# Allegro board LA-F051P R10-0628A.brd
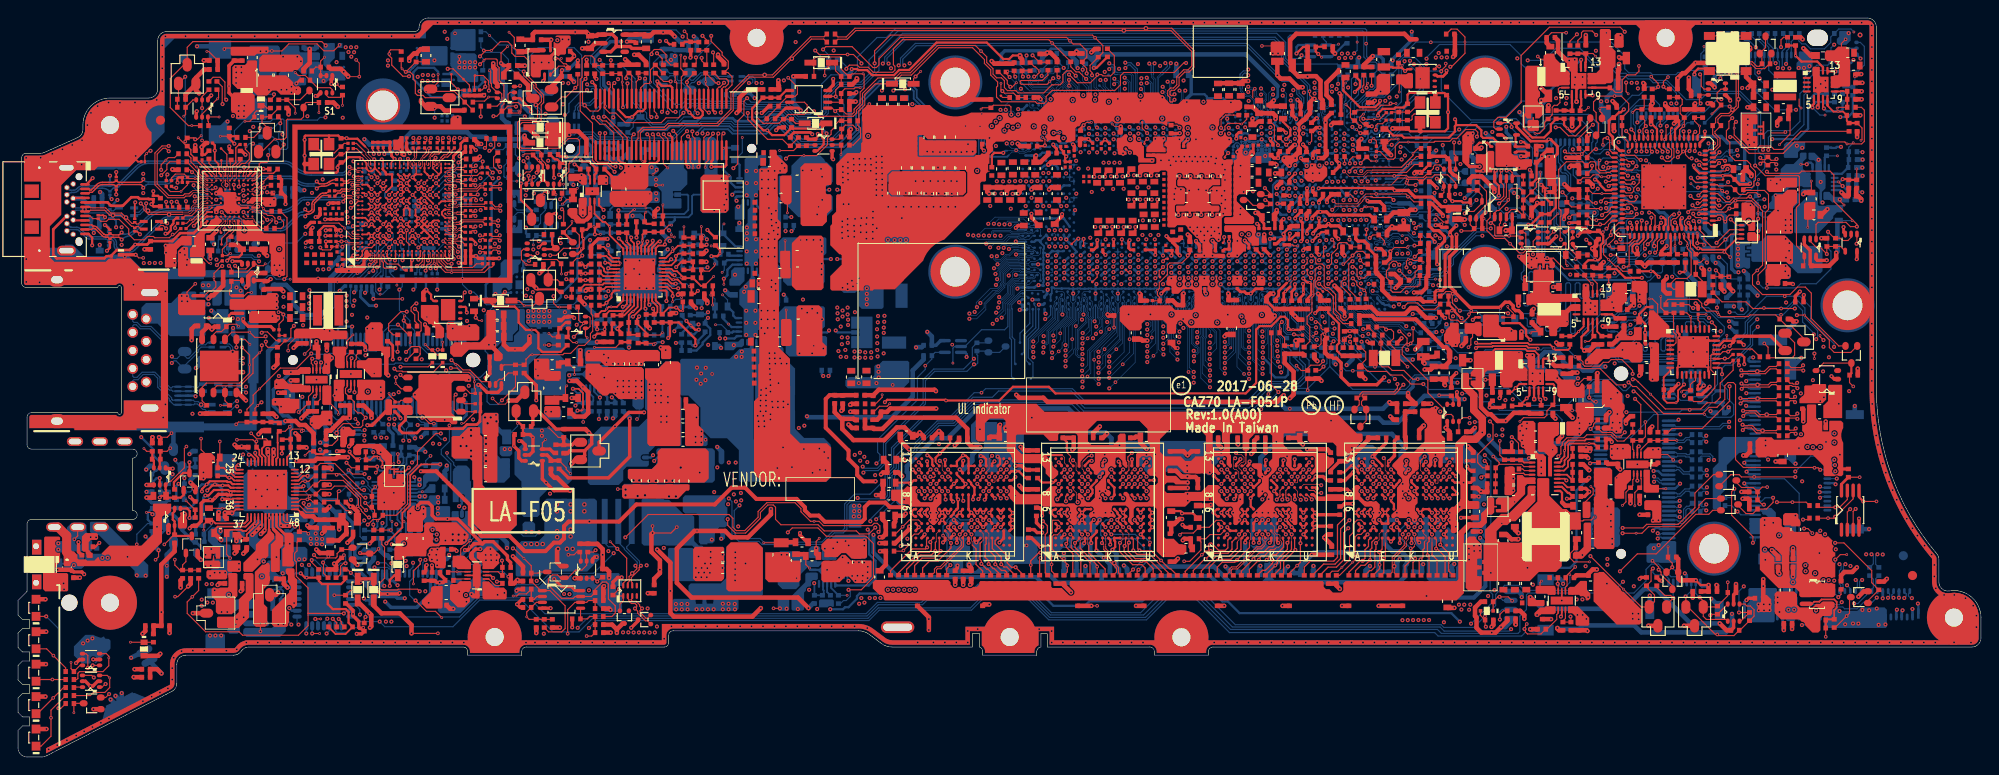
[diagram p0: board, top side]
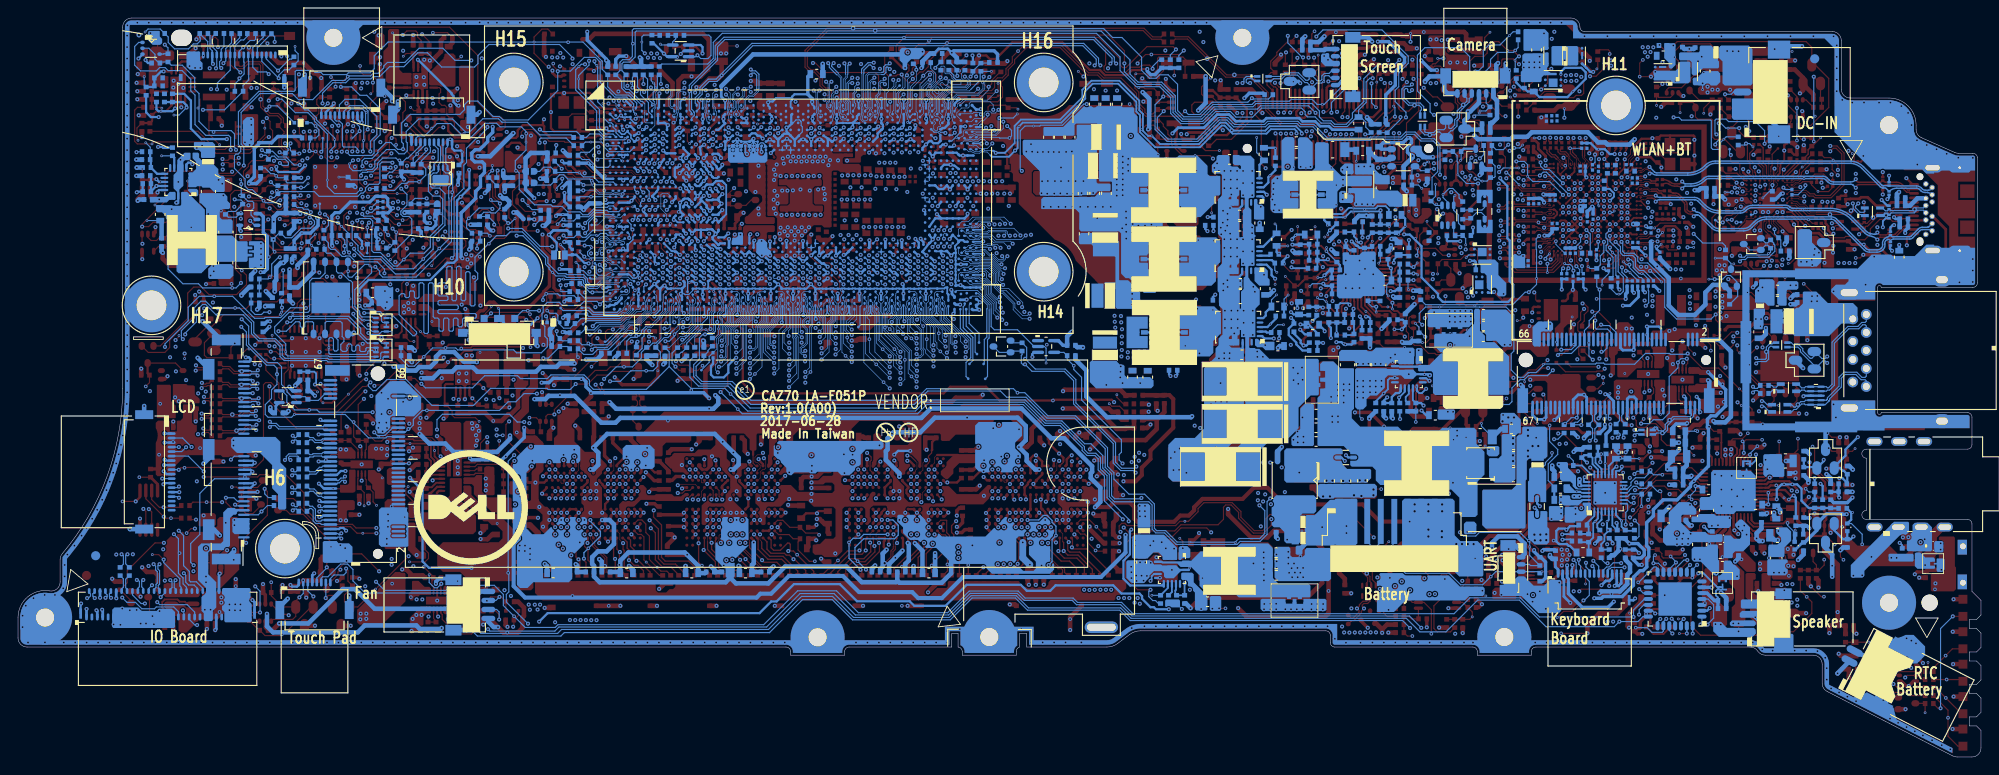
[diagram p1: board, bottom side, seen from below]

Outline 217.81 x 82 mm; copper layers: TOP, GND1, IN1, GND2, IN2, IN3, VCC, IN4, GND3, BOTTOM. Coordinates in mm from the lower left corner of the outline.
Outline path: 0,17.38 1,18.38 1,25.86 arc(1.15,26.21) 1.5,26.36 12.72,26.36 arc(13.22,26.86) 12.72,27.36 12.72,33.16 arc(13.22,33.66) 12.72,34.16 1.5,34.16 arc(1.15,34.31) 1,34.66 1,37.71 arc(1.15,38.06) 1.5,38.21 11.07,38.21 arc(11.27,38.01) 11.47,38.21 11.47,52.11 arc(11.27,52.31) 11.07,52.11 0.9,52.11 arc(0.55,52.26) 0.4,52.61 0.4,66.49 arc(0.55,66.84) 0.9,66.99 2.49,66.99 arc(2.7,67.01) 2.9,67.08 6.61,68.73 arc(7.04,69.09) 7.2,69.64 7.2,70.12 arc(8.08,72.24) 10.2,73.12 14.5,73.12 arc(15.21,73.41) 15.5,74.12 15.5,79.5 arc(15.79,80.21) 16.5,80.5 44,80.5 arc(44.35,80.65) 44.5,81 arc(44.79,81.71) 45.5,82 205.2,82 arc(205.91,81.71) 206.2,81 206.2,40.92 arc(207.93,31.15) 212.9,22.56 arc(213.08,22.26) 213.14,21.91 213.14,19.41 arc(213.49,18.65) 214.31,18.43 arc(216.75,17.76) 217.81,15.47 217.81,13.2 arc(217.52,12.49) 216.81,12.2 132.59,12.2 arc(132.24,12.05) 132.09,11.7 132.09,11.3 126.09,11.3 126.09,11.7 arc(125.94,12.05) 125.59,12.2 114.2,12.2 114.2,13.7 113.5,13.7 113.5,12.2 arc(113.17,12.04) 113.04,11.7 113.04,11.3 107.04,11.3 107.04,11.72 arc(106.94,12.02) 106.68,12.2 106.68,13.7 105.88,13.7 105.88,12.2 96.99,12.2 arc(96.36,12.3) 95.79,12.6 94.46,13.6 arc(93.89,13.9) 93.26,14 72.7,14 arc(72.35,13.85) 72.2,13.5 72.2,12.7 arc(72.05,12.35) 71.7,12.2 56.39,12.2 arc(56.04,12.05) 55.89,11.7 55.89,11.3 49.89,11.3 49.89,11.7 arc(49.74,12.05) 49.39,12.2 25.61,12.2 arc(25.14,12.08) 24.78,11.75 arc(24.41,11.42) 23.94,11.3 18.62,11.3 arc(17.91,11.01) 17.62,10.3 17.62,8.17 arc(17.47,7.65) 17.08,7.28 3.12,0.11 arc(2.89,0.03) 2.66,0 1,0 arc(0.29,0.29) 0,1 0,2.95 0.5,3.45 1.3,3.45 1.3,4.45 0.5,4.45 0,4.95 0,6.55 0.5,7.05 1.3,7.05 1.3,8.05 0.5,8.05 0,8.55 0,10.15 0.5,10.65 1.3,10.65 1.3,11.65 0.5,11.65 0,12.15 0,13.75 0.5,14.25 1.3,14.25 1.3,15.25 0.5,15.25 0,15.75 0,17.38

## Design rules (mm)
constraint set DEFAULT: min track width 0.127
net group 12C: nets I2C1_SDA I2C1_SDA_TP
net group CLK1_PCIE_WLAN: nets CLK1_PCIE_WLAN CLK1_PCIE_WLAN#
net group CLK_ITPXDP: nets CLK_ITPXDP_N CLK_ITPXDP_P
net group CLK_PCIE_MMI: nets CLK_PCIE_MMI CLK_PCIE_MMI#
net group CLK_PCIE_SSD: nets CLK_PCIE_SSD CLK_PCIE_SSD#
net group CLKO_PCIE_TBT: nets CLK0_PCIE_TBT CLK0_PCIE_TBT#
net group CPU_DDI1_AUX: nets CPU_DDI1_AUXN CPU_DDI1_AUXP
net group CPU_DDI2_AUX: nets CPU_DDI2_AUXN CPU_DDI2_AUXP
net group DDI1_PTX_TBRX_P0: nets DDI1_PTX_TBRX_N0 DDI1_PTX_TBRX_P0
net group DDI1_PTX_TBRX_P1: nets DDI1_PTX_TBRX_N1 DDI1_PTX_TBRX_P1
net group DDI1_PTX_TBRX_P2: nets DDI1_PTX_TBRX_N2 DDI1_PTX_TBRX_P2
net group DDI1_PTX_TBRX_P3: nets DDI1_PTX_TBRX_N3 DDI1_PTX_TBRX_P3
net group DDI2_PTX_TBRX_P0: nets DDI2_PTX_TBRX_N0 DDI2_PTX_TBRX_P0
net group DDI2_PTX_TBRX_P1: nets DDI2_PTX_TBRX_N1 DDI2_PTX_TBRX_P1
net group DDI2_PTX_TBRX_P2: nets DDI2_PTX_TBRX_N2 DDI2_PTX_TBRX_P2
net group DDI2_PTX_TBRX_P3: nets DDI2_PTX_TBRX_N3 DDI2_PTX_TBRX_P3
net group DIFFPAIR0: nets EDP_AUXN EDP_AUXP
net group DIFFPAIR2: nets EDP_AUXN_CONN EDP_AUXP_CONN
net group DIFFPAIR6: nets CPU_DDI1_AUXN_C CPU_DDI1_AUXP_C
net group DIFFPAIR7: nets CLK_ITPXDP_N_R CLK_ITPXDP_P_R
net group DIFFPAIR8: nets PCIE_PRX_TBTX_N1_C PCIE_PRX_TBTX_P1_C
net group DIFFPAIR9: nets PCIE_PRX_TBTX_N2_C PCIE_PRX_TBTX_P2_C
net group DIFFPAIR10: nets PCIE_PTX_CARDRX_N6_C PCIE_PTX_CARDRX_P6_C
net group DIFFPAIR11: nets PCIE_PTX_SSDRX_N11_C PCIE_PTX_SSDRX_P11_C
net group DIFFPAIR12: nets PCIE_PTX_SSDRX_N10_C PCIE_PTX_SSDRX_P10_C
net group DIFFPAIR13: nets PCIE_PTX_WLANRX_N5_C PCIE_PTX_WLANRX_P5_C
net group DIFFPAIR14: nets PCIE_PTX_SSDRX_N9_C PCIE_PTX_SSDRX_P9_C
net group DIFFPAIR15: nets PCIE_PTX_TBRX_N1_C PCIE_PTX_TBRX_P1_C
net group DIFFPAIR16: nets PCIE_PTX_TBRX_N2_C PCIE_PTX_TBRX_P2_C
net group DIFFPAIR17: nets USB20_N2_CONN USB20_P2_CONN
net group DIFFPAIR18: nets USB20_N3_R USB20_P3_R
net group DIFFPAIR19: nets USB20_N4_CONN USB20_P4_CONN
net group DIFFPAIR20: nets USB20_N5_CONN USB20_P5_CONN
net group DIFFPAIR21: nets USB3RN2_RC_CON USB3RP2_RC_CON
net group DIFFPAIR22: nets USB3TN2_C USB3TP2_C
net group DIFFPAIR23: nets USB3TN2_RC_CON USB3TP2_RC_CON
net group DP_CPU_DDI2_AUXN_C: nets CPU_DDI2_AUXN_C CPU_DDI2_AUXP_C
net group DP_EDP_TXN_P0_CONN: nets EDP_TXN_P0_CONN EDP_TXP_P0_CONN
net group DP_EDP_TXN_P1_CONN: nets EDP_TXN_P1_CONN EDP_TXP_P1_CONN
net group DP_EDP_TXN_P2_CONN: nets EDP_TXN_P2_CONN EDP_TXP_P2_CONN
net group DP_EDP_TXN_P3_CONN: nets EDP_TXN_P3_CONN EDP_TXP_P3_CONN
net group DP_TBT_I2C_B_N_R: nets TBT_I2C_B_N_R TBT_I2C_B_P_R
net group DP_TBT_USB2_T_N_R: nets TBT_USB2_T_N_R TBT_USB2_T_P_R
net group EDP_TX_P1: nets EDP_TXN_P1 EDP_TXP_P1
net group EDP_TX_P2: nets EDP_TXN_P2 EDP_TXP_P2
net group EDP_TX_P3: nets EDP_TXN_P3 EDP_TXP_P3
net group EPD_TX_P0: nets EDP_TXN_P0 EDP_TXP_P0
net group MEM_SMBCLKDATA: nets MEM_SMBCLK MEM_SMBDATA
net group PBAT_SMBCLKDAT: nets PBAT_SMBCLK PBAT_SMBDAT
net group PCIE_PRX_CARDTX_P6: nets PCIE_PRX_CARDTX_N6 PCIE_PRX_CARDTX_P6
net group PCIE_PRX_SSDTX_11: nets PCIE_PRX_SSDTX_N11 PCIE_PRX_SSDTX_P11
net group PCIE_PRX_SSDTX_P9: nets PCIE_PRX_SSDTX_N9 PCIE_PRX_SSDTX_P9
net group PCIE_PRX_SSDTX_P10: nets PCIE_PRX_SSDTX_N10 PCIE_PRX_SSDTX_P10
net group PCIE_PRX_TBTX_P1: nets PCIE_PRX_TBTX_N1 PCIE_PRX_TBTX_P1
net group PCIE_PRX_TBTX_P2: nets PCIE_PRX_TBTX_N2 PCIE_PRX_TBTX_P2
net group PCIE_PRX_WLANTX_P5: nets PCIE_PRX_WLANTX_N5 PCIE_PRX_WLANTX_P5
net group PCIE_PTX_CARDRX_P6: nets PCIE_PTX_CARDRX_N6 PCIE_PTX_CARDRX_P6
net group PCIE_PTX_SSDRX_11: nets PCIE_PTX_SSDRX_N11 PCIE_PTX_SSDRX_P11
net group PCIE_PTX_SSDRX_P9: nets PCIE_PTX_SSDRX_N9 PCIE_PTX_SSDRX_P9
net group PCIE_PTX_SSDRX_P10: nets PCIE_PTX_SSDRX_N10 PCIE_PTX_SSDRX_P10
net group PCIE_PTX_TBRX_P1: nets PCIE_PTX_TBRX_N1 PCIE_PTX_TBRX_P1
net group PCIE_PTX_TBRX_P2: nets PCIE_PTX_TBRX_N2 PCIE_PTX_TBRX_P2
net group PCIE_PTX_WLANRX_P5: nets PCIE_PTX_WLANRX_N5 PCIE_PTX_WLANRX_P5
net group REM_DIODE1: nets REM_DIODE1_N REM_DIODE1_P
net group REM_DIODE2: nets REM_DIODE2_N REM_DIODE2_P
net group REM_DIODE3: nets REM_DIODE3_N REM_DIODE3_P
net group REM_DIODE4: nets REM_DIODE4_N REM_DIODE4_P
net group SATA_PRX_SSDTX_2: nets SATA_PRX_SSDTX_N2 SATA_PRX_SSDTX_P2
net group SATA_PTX_SSDRX_2: nets SATA_PTX_SSDRX_N2 SATA_PTX_SSDRX_P2
net group SMB_CLKDAT: nets CLK_SMB DAT_SMB
net group SML1_SMBCLKDAT: nets SML1_SMBCLK SML1_SMBDAT
net group SPACING-18: nets PECI_EC PECI_EC_R
net group TBT_12C_CLKDATA: nets TBT_I2C_CLK TBT_I2C_DATA
net group TBT_I2C_B: nets TBT_I2C_B_N TBT_I2C_B_P
net group TBT_USB2_T: nets TBT_USB2_T_N TBT_USB2_T_P
net group TBT_USB3_RX1: nets TBT_USB3_RX1_N TBT_USB3_RX1_P
net group TBT_USB3_RXO_NP_R: nets TBT_USB3_RX0_N TBT_USB3_RX0_P
net group TBT_USB3_TX0_P_C: nets TBT_USB3_TX0_N_C TBT_USB3_TX0_P_C
net group TBT_USB3_TX1: nets TBT_USB3_TX1_N TBT_USB3_TX1_P
net group TBT_USB3_TX1_N_C: nets TBT_USB3_TX1_N_C TBT_USB3_TX1_P_C
net group TBT_USB3_TXO_P: nets TBT_USB3_TX0_N TBT_USB3_TX0_P
net group USB2.0_P1: nets USB20_N1 USB20_P1
net group USB2.0_P2: nets USB20_N2 USB20_P2
net group USB2.0_P3: nets USB20_N3 USB20_P3
net group USB2.0_P4: nets USB20_N4 USB20_P4
net group USB2.0_P5: nets USB20_N5 USB20_P5
net group USB3.0_R1: nets USB3RN1 USB3RP1
net group USB3.0_R2: nets USB3RN2 USB3RP2
net group USB3.0_T1: nets USB3TN1 USB3TP1
net group USB3.0_T2: nets USB3TN2 USB3TP2
net group USB_2.0: nets TBT_USB2_D_N TBT_USB2_D_P
net group 12C_15: nets HDA_BIT_CLK HDA_BIT_CLK_R I2C1_SCK I2C1_SCK_TP PCH_SPI_CLK PCH_SPI_CLK_TPM SPI_CLK_VROM
net group 24MHZ: nets CLK_LPC_DEBUG CLK_PCI_MEC PCI_CLK_LPC0 PCI_CLK_LPC1 XTAL24_IN XTAL24_OUT
net group COMP-20-25: nets SM_RCOMP0 SM_RCOMP1 SM_RCOMP2
net group DDRA_CKE: nets DDR_A_CKE0 DDR_A_CKE1 DDR_A_CKE2 DDR_A_CKE3
net group DDRB-D6: nets DDR_B_D48 DDR_B_D49 DDR_B_D50 DDR_B_D51 DDR_B_D52 DDR_B_D53 DDR_B_D54 DDR_B_D55
net group DDRB-D7: nets DDR_B_D56 DDR_B_D57 DDR_B_D58 DDR_B_D59 DDR_B_D60 DDR_B_D61 DDR_B_D62 DDR_B_D63
net group DDRB_CKE: nets DDR_B_CKE0 DDR_B_CKE1 DDR_B_CKE2 DDR_B_CKE3
net group DP1_AR_TBT: nets DDI1_PTX_TBRX_N0_C DDI1_PTX_TBRX_N1_C DDI1_PTX_TBRX_N2_C DDI1_PTX_TBRX_N3_C DDI1_PTX_TBRX_P0_C DDI1_PTX_TBRX_P1_C DDI1_PTX_TBRX_P2_C DDI1_PTX_TBRX_P3_C
net group DP2_AR_TBT: nets DDI2_PTX_TBRX_N0_C DDI2_PTX_TBRX_N1_C DDI2_PTX_TBRX_N2_C DDI2_PTX_TBRX_N3_C DDI2_PTX_TBRX_P0_C DDI2_PTX_TBRX_P1_C DDI2_PTX_TBRX_P2_C DDI2_PTX_TBRX_P3_C
net group HDA: nets HDA_SDIN0 HDA_SDOUT HDA_SDOUT_R HDA_SYNC HDA_SYNC_R
net group R_DDRA-CLK-UD19: nets DDR_A_DQS0 DDR_A_DQS1 DDR_A_DQS2 DDR_A_DQS3
net group R_DDRA-CLK-UD20: nets DDR_A_DQS4 DDR_A_DQS5 DDR_A_DQS6 DDR_A_DQS7
net group R_DDRA-D0: nets DDR_A_D0 DDR_A_D1 DDR_A_D2 DDR_A_D3 DDR_A_D4 DDR_A_D5 DDR_A_D6 DDR_A_D7
net group R_DDRA-D1: nets DDR_A_D8 DDR_A_D9 DDR_A_D10 DDR_A_D11 DDR_A_D12 DDR_A_D13 DDR_A_D14 DDR_A_D15
net group R_DDRA-D2: nets DDR_A_D16 DDR_A_D17 DDR_A_D18 DDR_A_D19 DDR_A_D20 DDR_A_D21 DDR_A_D22 DDR_A_D23
net group R_DDRA-D3: nets DDR_A_D24 DDR_A_D25 DDR_A_D26 DDR_A_D27 DDR_A_D28 DDR_A_D29 DDR_A_D30 DDR_A_D31
net group R_DDRA-D4: nets DDR_A_D32 DDR_A_D33 DDR_A_D34 DDR_A_D35 DDR_A_D36 DDR_A_D37 DDR_A_D38 DDR_A_D39
net group R_DDRA-D5: nets DDR_A_D40 DDR_A_D41 DDR_A_D42 DDR_A_D43 DDR_A_D44 DDR_A_D45 DDR_A_D46 DDR_A_D47
net group R_DDRA-D6: nets DDR_A_D48 DDR_A_D49 DDR_A_D50 DDR_A_D51 DDR_A_D52 DDR_A_D53 DDR_A_D54 DDR_A_D55
net group R_DDRA-D7: nets DDR_A_D56 DDR_A_D57 DDR_A_D58 DDR_A_D59 DDR_A_D60 DDR_A_D61 DDR_A_D62 DDR_A_D63
net group R_DDRA-DQS0: nets DDR_A_DQS#0
net group R_DDRA-DQS1: nets DDR_A_DQS#1
net group R_DDRA-DQS2: nets DDR_A_DQS#2
net group R_DDRA-DQS3: nets DDR_A_DQS#3
net group R_DDRA-DQS4: nets DDR_A_DQS#4
net group R_DDRA-DQS5: nets DDR_A_DQS#5
net group R_DDRA-DQS6: nets DDR_A_DQS#6
net group R_DDRA-DQS7: nets DDR_A_DQS#7
net group R_DDRB-CLK-UD21: nets DDR_B_DQS0 DDR_B_DQS1 DDR_B_DQS2 DDR_B_DQS3
net group R_DDRB-CLK-UD22: nets DDR_B_DQS4 DDR_B_DQS5 DDR_B_DQS6 DDR_B_DQS7
net group R_DDRB-D0: nets DDR_B_D0 DDR_B_D1 DDR_B_D2 DDR_B_D3 DDR_B_D4 DDR_B_D5 DDR_B_D6 DDR_B_D7
net group R_DDRB-D1: nets DDR_B_D8 DDR_B_D9 DDR_B_D10 DDR_B_D11 DDR_B_D12 DDR_B_D13 DDR_B_D14 DDR_B_D15
net group R_DDRB-D2: nets DDR_B_D16 DDR_B_D17 DDR_B_D18 DDR_B_D19 DDR_B_D20 DDR_B_D21 DDR_B_D22 DDR_B_D23
net group R_DDRB-D3: nets DDR_B_D24 DDR_B_D25 DDR_B_D26 DDR_B_D27 DDR_B_D28 DDR_B_D29 DDR_B_D30 DDR_B_D31
net group R_DDRB-D4: nets DDR_B_D32 DDR_B_D33 DDR_B_D34 DDR_B_D35 DDR_B_D36 DDR_B_D37 DDR_B_D38 DDR_B_D39
net group R_DDRB-D5: nets DDR_B_D40 DDR_B_D41 DDR_B_D42 DDR_B_D43 DDR_B_D44 DDR_B_D45 DDR_B_D46 DDR_B_D47
net group R_DDRB-DQS0: nets DDR_B_DQS#0
net group R_DDRB-DQS1: nets DDR_B_DQS#1
net group R_DDRB-DQS2: nets DDR_B_DQS#2
net group R_DDRB-DQS3: nets DDR_B_DQS#3
net group R_DDRB-DQS4: nets DDR_B_DQS#4
net group R_DDRB-DQS5: nets DDR_B_DQS#5
net group R_DDRB-DQS6: nets DDR_B_DQS#6
net group R_DDRB-DQS7: nets DDR_B_DQS#7
net group SPACING-12: nets H_CATERR# H_PROCHOT# H_PROCHOT#_EC H_PROCHOT#_R H_THERMTRIP# H_VCCST_PWRGD PCIE_RCOMPN PCIE_RCOMPP VCCST_PWRGD XDP_OBS0 XDP_OBS0_R XDP_OBS1 XDP_OBS1_R XDP_OBS2_R XDP_OBS3_R
net group SPACING-15: nets DMIC_CLK_CODEC DMIC_CLK_CODEC_R PCH_RTCRST# PCH_RTCX1 PCH_RTCX2 SRTCRST# USBCOMP XCLK_BIASREF
net group SPACING-20: nets +V_DDR_REF_CA +V_DDR_REFA_R +V_DDR_REFB_R +VREFCA +VREFDQ_A +VREFDQ_B N40373501
net group SPACING-25: nets EDP_COMP
net group SPI_PCH: nets PCH_SPI_CS0# PCH_SPI_DO2_XDP PCH_SPI_DO_XDP PCH_SPI_IO2 PCH_SPI_IO3 PCH_SPI_SI PCH_SPI_SI_TPM PCH_SPI_SO PCH_SPI_SO_TPM RESET_OUT#_R SPI_IO2_VROM SPI_IO3_VROM SPI_SI_VROM SPI_SO_VROM
net group UART: nets UART0_TX
net group W20: nets +1.8VA +3V_VC +3VLP +3VS_AUDIO +3VS_TP +AVDD1 +AVDD2 +DC_IN +DC_IN_SS +DVDD +RTCVCC +VBUS_DC_SS ALW_PWRGD_3V_5V BATBTN# BATDRV#
nets with their own width: min track width 0.508; nets GND

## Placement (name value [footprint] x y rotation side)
C2  -  [C_0402]  27.28 50.94 90 top
C3  -  [C_0402]  19.48 51.32 0 bottom
C4  -  [C_0402]  54.45 70.27 0 bottom
C5  -  [C_0402]  74.4 78.44 0 bottom
C6  -  [C_0402]  193.09 33.87 180 top
C7  -  [C_0402]  186.74 18.37 180 top
C8  -  [C_0603]  63.48 80.03 270 top
C94  -  [C_0603]  181.46 43.14 180 top
C95  -  [C_0201]  186.39 40.81 270 top
C96  -  [C_0201]  190.31 46.06 0 top
C97  -  [C_0201]  181.17 45.83 180 top
C98  -  [C_0201]  182.61 39.99 0 top
C135  -  [C_0201]  190.31 44.66 0 top
C265  -  [C_0402]  19.48 50.43 0 bottom
C303  -  [C_B2]  19.94 48.35 180 bottom
C352  -  [C_0402]  46.63 16.85 0 top
C355  -  [C_0402]  48.31 19.59 180 top
C375  -  [C_0402]  45.95 20.48 270 top
C376  -  [C_0402]  47.22 21.98 90 bottom
C377  -  [C_0402]  45.06 20.48 270 top
C397  -  [C_0402]  9.32 61.17 180 bottom
C398  -  [C_0402]  9.02 58.82 180 bottom
C401  -  [C_0402]  9.02 59.71 180 bottom
C402  -  [C_0402]  9.32 62.06 180 bottom
C612  -  [C_0402]  196.2 25.1 90 top
C613  -  [C_0402]  199.67 15.2 0 top
C614  -  [C_0402]  197.21 50.5 0 top
C615  -  [C_0402]  196.06 52.54 180 top
C616  -  [C_0402]  190.63 48.09 270 bottom
C617  -  [C_0402]  189.59 50.05 90 bottom
C618  -  [C_0201]  18.29 59.81 180 top
C621  -  [C_0402]  24.49 40.34 180 bottom
C623  -  [C_0402]  24.49 41.23 180 bottom
C712  -  [C_0603]  33.12 46.82 270 top
C713  -  [C_0402]  49.84 46.66 270 top
C715  -  [C_0402]  31.09 46.82 270 top
C716  -  [C_0603]  48.69 46.66 270 top
C719  -  [C_0603]  175.46 23.71 180 top
C720  -  [C_0402]  175.16 25.66 180 top
C721  -  [C_0402]  176.12 41.55 180 top
C722  -  [C_0402]  175.16 24.77 180 top
C962  -  [C_0603]  26.14 50.06 270 top
C963  -  [C_0402]  27.28 50.07 270 top
C1060  -  [C_0402]  196.32 37.42 180 top
C1061  -  [C_0402]  196.32 39.2 180 top
C1062  -  [C_0402]  196.32 38.31 180 top
C1063  -  [C_0402]  196.32 40.09 180 top
C1064  -  [C_0402]  196.32 36.53 180 top
C1065  -  [C_0402]  196.32 35.65 180 top
C1066  -  [C_0402]  196.32 41.87 180 top
C1067  -  [C_0402]  196.32 40.98 180 top
C1068  -  [C_0402]  196.32 43.65 180 top
C1069  -  [C_0402]  196.32 42.76 180 top
C1102  -  [C_0402]  166.17 15.33 180 top
C1143  -  [C_0603]  195.81 34.18 270 top
C1145  -  [C_0402]  193.09 34.76 180 top
C1158  -  [C_0402]  177.52 33.44 270 top
C1159  -  [C_0402]  167.82 17.1 180 top
C1160  -  [C_0402]  37.82 39.91 270 top
C1161  -  [C_0402]  181.79 26.88 180 top
C1162  -  [C_0402]  181.97 33.56 270 top
C1163  -  [C_0402]  179.93 29.88 270 top
C1164  -  [C_0402]  176.25 31.76 90 top
C1166  -  [C_0402]  35.79 39.91 270 top
C1167  -  [C_0402]  36.99 44.93 90 top
C1168  -  [C_0402]  198.02 39.56 270 top
C1169  -  [C_0402]  30.96 42.71 270 top
C1199  -  [C_0402]  51.23 22.31 180 top
C1200  -  [C_0402]  47.17 23.05 0 top
C1201  -  [C_0402]  51.87 17.87 180 top
C1203  -  [C_0402]  60.35 78.32 0 top
C1204  -  [C_0402]  60.3 75.51 0 top
C1205  -  [C_0603]  24.28 28 0 bottom
C1208  -  [C_0402]  57.13 79.59 0 top
C1211  -  [C_0402]  199.67 36.53 0 top
C1212  -  [C_0402]  33.12 39.28 270 top
C1213  -  [C_0402]  34.21 44.41 180 top
C1214  -  [C_0402]  32.23 39.28 270 top
C1215  -  [C_0402]  34.27 46.64 270 top
C1216  -  [C_0402]  41 45.22 90 top
C1217  -  [C_0402]  29.57 39.51 90 top
C1218  -  [C_0402]  34.27 37.12 270 top
C1220  -  [C_0402]  54.48 76.73 0 top
C1221  -  [C_0402]  54.45 69.31 0 bottom
C1222  -  [C_0402]  74.4 79.33 0 bottom
C1223  -  [C_0402]  68.56 80.17 270 top
C1225  -  [C_0402]  187.6 18.37 0 top
C1226  -  [C_0402]  181.84 19.01 90 top
C1229  -  [C_0402]  180.7 19.01 90 top
C1254  -  [C_0402]  169.14 16.21 270 top
C1256  -  [C_0402]  173.2 14.97 270 top
C1257  -  [C_0402]  170.87 19.9 180 top
C1258  -  [C_0402]  171.73 19.9 0 top
C1264  -  [C_0402]  175.18 20.15 180 top
C1273  -  [C_0402]  69.84 38.88 180 bottom
C1274  -  [C_0402]  61.24 57.29 90 bottom
C1275  -  [C_0402]  73.19 39.65 0 top
C1278  -  [C_0402]  47.73 20.48 180 top
C1279  -  [C_0402]  15.8 61.1 90 top
C1280  -  [C_0402]  14.71 57.25 270 top
C1289  -  [C_0402]  27.41 52.79 90 top
C1292  -  [C_0402]  178.92 29.88 270 top
C1293  -  [C_0402]  37.88 44.93 90 top
C1297  -  [C_0402]  31.98 46.82 270 top
C1298  -  [C_0402]  50.72 46.66 270 top
C1301  -  [C_0402]  43.54 36.86 270 bottom
C1302  -  [C_0402]  42.39 36.86 270 bottom
C1304  -  [C_0402]  176.12 40.66 180 top
C1309  -  [C_0402]  15.9 14.56 0 top
C1321  -  [C_0402]  193.65 17.61 180 top
C1322  -  [C_0402]  195.94 14.82 0 top
C1324  -  [C_0402]  195.3 21.09 90 top
C1325  -  [C_0402]  196.95 21.09 90 top
C1339  -  [C_0603]  20.23 57.24 180 top
C1341  -  [C_0402]  29.57 63.1 0 bottom
C1345  -  [C_0201]  20.42 66.25 90 top
C1346  -  [C_0402]  20.88 47.84 180 top
C1347  -  [C_0603]  21.34 57.61 270 top
C1348  -  [C_0603]  24.84 57.74 270 top
C1349  -  [C_0603]  27.28 57.74 270 top
C1350  -  [C_0603]  26.06 57.74 270 top
C1353  -  [C_0603]  18.06 54.8 180 top
C1354  -  [C_0201]  21.58 68.13 180 top
C1984  -  [C_0201]  181.31 49.35 90 top
C1985  -  [C_0603]  181.27 48.43 180 top
C2973  -  [C_0402]  14.66 9.74 180 top
C2982  -  [C_0603]  197.27 24.54 90 top
C2983  -  [C_0402]  5.23 19.9 0 top
C2984  -  [C_0402]  29.57 62.21 0 bottom
CA2  -  [C_0805]  28.08 22.82 0 bottom
CA3  -  [C_0402]  26.9 23.28 270 bottom
CA4  -  [C_0402]  33.12 26.32 270 top
CA5  -  [C_0805]  35.95 26.37 0 top
CA6  -  [C_0805]  32.65 33.36 0 bottom
CA7  -  [C_0402]  33.05 31.96 0 bottom
CA23  -  [C_0402]  36.37 28.28 180 top
CA24  -  [C_0402]  33.96 32.09 180 top
CA25  -  [C_0402]  33.96 27.39 180 top
CA27  -  [C_0402]  33.96 29.17 180 top
CA28  -  [C_0402]  6.96 23.15 270 bottom
CA29  -  [C_0402]  19.69 22.89 90 bottom
CA30  -  [C_0402]  33.96 30.18 180 top
CA31  -  [C_0402]  34.9 26.32 270 top
CA32  -  [C_0402]  111.86 76.08 90 bottom
CA33  -  [C_0402]  28.07 37.17 90 top
CA34  -  [C_0402]  28.99 37.05 270 top
CA35  -  [C_0402]  111.81 73.19 0 top
CA40  -  [C_0402]  15.79 33.92 90 top
CA42  -  [C_0402]  34.01 26.32 270 top
CA53  -  [C_0402]  24.87 19.26 0 top
CA54  -  [C_0402]  28.63 19.77 180 top
CA55  -  [C_0402]  22.96 19.26 0 top
CA56  -  [C_0402]  29.49 19.77 0 top
CA68  -  [C_0402]  7.09 22.39 270 top
CA69  -  [C_0402]  14.83 24.16 270 bottom
CA70  -  [C_0402]  19.66 28.36 270 top
CA71  -  [C_0402]  18.45 30.32 270 bottom
CA72  -  [C_0402]  182.61 40.75 0 top
CA74  -  [C_0603]  16.42 28.98 180 top
CA78  -  [C_0402]  23.14 26.46 180 top
CA80  -  [C_0402]  25.38 24.16 270 top
CA82  -  [C_0603]  24.23 24.66 270 top
CA83  -  [C_0603]  22.71 26.44 90 bottom
CA86  -  [C_0603]  21.18 26.22 90 top
CA87  -  [C_0402]  22.15 31.2 180 top
CA97  -  [C_0402]  32.74 27.21 270 bottom
CA98  -  [C_0805]  33.8 26.76 0 bottom
CA99  -  [C_0805]  30.46 26.54 90 bottom
CA100  -  [C_0402]  29.06 26.3 90 bottom
CA101  -  [C_0805]  21.73 24.6 0 bottom
CA102  -  [C_0805]  22.54 32.85 180 bottom
CA103  -  [C_0402]  22.15 31.45 180 bottom
CA104  -  [C_0402]  33.05 31.07 0 bottom
CA105  -  [C_0402]  33.05 30.18 0 bottom
CA106  -  [C_0402]  30.25 35.26 0 top
CA107  -  [C_0603]  27.66 36.22 270 top
CA108  -  [C_0603]  29.5 29.68 0 bottom
CA109  -  [C_0603]  22.39 33.23 180 top
CA110  -  [C_0603]  21.76 24.85 0 top
CA111  -  [C_0402]  29.82 24.11 90 bottom
CA112  -  [C_0805]  31.22 24.43 270 bottom
CC4  -  [C_0402]  158.6 45.55 180 bottom
CC5  -  [C_0402]  158.6 46.44 180 bottom
CC8  -  [C_0402]  185.65 56.27 90 bottom
CC10  -  [C_0402]  187.68 52.1 270 bottom
CC21  -  [C_0402]  154.17 70.66 270 top
CC22  -  [C_0402]  154.18 71.57 90 top
CC23  -  [C_0402]  152.12 45.93 0 top
CC24  -  [C_0402]  147.17 46.31 90 top
CC25  -  [C_0402]  148.44 46.31 90 top
CC26  -  [C_0402]  151.23 45.93 180 top
CC27  -  [C_0402]  141.71 44.54 90 bottom
CC28  -  [C_0402]  67.79 75.9 90 top
CC29  -  [C_0402]  67.67 69.3 90 bottom
CC31  -  [C_0603]  134.67 48.28 270 top
CC32  -  [C_0402]  66.78 69.3 90 bottom
CC33  -  [C_0402]  66.78 75.83 90 top
CC34  -  [C_0603]  127.99 47.39 270 top
CC35  -  [C_0603]  124.05 47.77 270 top
CC95  -  [C_0201]  156.31 55.74 90 bottom
CC125  -  [C_0201]  140.49 56.84 90 top
CC174  -  [C_0402]  124.56 49.74 90 top
CC175  -  [C_0402]  129.26 49.23 90 top
CC176  -  [C_0402]  135.23 49.79 90 top
CC177  -  [C_0402]  138.53 49.67 90 top
CC178  -  [C_0402]  134.34 49.79 90 top
CC179  -  [C_0402]  122.53 48.98 180 top
CC181  -  [C_0201]  134.98 57.74 180 top
CC182  -  [C_0201]  135.99 56.47 0 top
CC185  -  [C_0201]  134.96 56.35 180 top
CC186  -  [C_0201]  128.63 56.22 180 top
CC194  -  [C_0402]  126.67 50.62 0 top
CC195  -  [C_0402]  142.31 71.35 180 top
CC199  -  [C_0402]  138.79 72.35 270 top
CC202  -  [C_0402]  139.04 66.79 270 top
CC203  -  [C_0402]  142.98 66.23 90 top
CC204  -  [C_0402]  151.61 54.87 90 top
CC205  -  [C_0402]  142.34 60.54 0 top
CC206  -  [C_0402]  141.33 61.43 0 top
CC209  -  [C_0402]  140.44 62.32 270 top
CC210  -  [C_0805]  151.55 78.27 270 top
CC211  -  [C_0402]  145.01 64.86 0 top
CC212  -  [C_0402]  155.68 61.05 0 bottom
CC213  -  [C_0402]  145.39 49.74 90 top
CC214  -  [C_0402]  146.79 49.79 90 top
CC217  -  [C_0402]  140.18 58.76 0 top
CC218  -  [C_0402]  141.07 63.78 180 top
CC220  -  [C_0402]  146.79 71.28 270 top
CC223  -  [C_0402]  141.96 58 90 top
CC224  -  [C_0402]  143.2 56.42 0 top
CC225  -  [C_0201]  158.55 59.36 270 top
CC240  -  [C_0402]  101.4 45.68 180 bottom
CC248  -  [C_0402]  136.88 58.63 90 top
CC249  -  [C_0402]  129.01 57.62 90 top
CC250  -  [C_0402]  135.1 58.63 90 top
CC251  -  [C_0402]  135.99 58.63 90 top
CC252  -  [C_0402]  128.12 57.36 90 top
CC253  -  [C_0402]  134.21 58.63 90 top
CC256  -  [C_0201]  135.28 52.56 270 top
CC257  -  [C_0201]  131.67 52.54 270 top
CC258  -  [C_0201]  127.61 52.54 270 top
CC259  -  [C_0201]  138.02 52.54 270 top
CC260  -  [C_0201]  125.88 50.64 180 top
CC261  -  [C_0201]  139.42 57.53 270 top
CC264  -  [C_0402]  145.18 67.18 180 top
CC265  -  [C_0402]  143.03 62.44 0 top
CC266  -  [C_0402]  143.61 45.42 270 bottom
CC267  -  [C_0402]  144.81 62.44 0 top
CC268  -  [C_0402]  144.37 58.89 180 top
CC269  -  [C_0402]  68.81 75.9 90 top
CC270  -  [C_0402]  144.5 49.74 90 top
CC271  -  [C_0805]  155.93 44.41 90 top
CC272  -  [C_0805]  153.77 60.41 270 top
CC273  -  [C_0805]  141.39 76.77 0 top
CC274  -  [C_0805]  139.74 77.2 90 top
CC279  -  [C_0603]  158.28 43.33 270 top
CC280  -  [C_0603]  157.07 43.33 270 top
CC281  -  [C_0201]  161.14 59.7 0 bottom
CC282  -  [C_0402]  142.31 72.22 180 top
CC283  -  [C_0402]  140.01 67.19 0 top
CD1  -  [C_0402]  118.05 35.41 180 top
CD2  -  [C_0603]  99.29 35.65 180 top
CD3  -  [C_0402]  97.35 31.58 180 top
CD4  -  [C_0603]  97.33 29.06 180 top
CD5  -  [C_0402]  122.5 35.41 0 top
CD6  -  [C_0603]  125.93 35.54 180 top
CD7  -  [C_0402]  127.83 33 90 top
CD8  -  [C_0603]  97.45 32.98 180 top
CD29  -  [C_0402]  112.12 30.95 90 top
CD30  -  [C_0603]  143.61 35.54 180 top
CD33  -  [C_0402]  100.5 35.41 0 top
CD34  -  [C_0603]  117.45 20.41 180 bottom
CD37  -  [C_0402]  106.85 35.41 0 top
CD38  -  [C_0603]  161.65 27.96 270 top
CD39  -  [C_0402]  186.67 27.26 180 bottom
CD41  -  [C_0402]  119.36 20.53 180 bottom
CD42  -  [C_0603]  127.96 27.28 270 top
CD43  -  [C_0402]  186.67 28.15 180 bottom
CD44  -  [C_0402]  186.67 35.77 180 bottom
CD45  -  [C_0402]  186.67 29.17 180 bottom
CD46  -  [C_0402]  186.67 30.06 180 bottom
CD47  -  [C_0402]  186.67 34.88 180 bottom
CD51  -  [C_0402]  186.67 31.96 180 bottom
CD53  -  [C_0402]  186.67 31.07 180 bottom
CD57  -  [C_0402]  146.66 31.58 270 top
CD58  -  [C_0603]  142.34 20.41 0 bottom
CD59  -  [C_0402]  148.89 35.41 0 top
CD60  -  [C_0603]  157.46 35.52 0 top
CD61  -  [C_0402]  145.64 28.79 90 top
CD62  -  [C_0603]  136.37 20.41 0 bottom
CD63  -  [C_0402]  130.91 33 90 top
CD64  -  [C_0603]  150.98 20.41 180 bottom
CD85  -  [C_0402]  135.36 20.53 180 bottom
CD86  -  [C_0603]  110.28 35.54 180 top
CD87  -  [C_0402]  146.66 28.79 90 top
CD88  -  [C_0603]  157.71 20.41 0 bottom
CD89  -  [C_0402]  141.45 20.53 180 bottom
CD90  -  [C_0603]  130.91 26.5 90 top
CD91  -  [C_0402]  145.77 22.44 90 top
CD92  -  [C_0603]  97.33 26.78 180 top
CD117  -  [C_0402]  105.33 35.39 180 top
CD118  -  [C_0402]  120.21 35.41 180 top
CD119  -  [C_0402]  138.4 35.41 180 top
CD120  -  [C_0402]  153.97 35.41 180 top
CD129  -  [C_0402]  147.68 17.69 270 top
CD132  -  [C_0402]  107.04 17.69 270 top
CD133  -  [C_0402]  99.8 17.69 270 top
CD135  -  [C_0402]  117.58 17.69 270 top
CD136  -  [C_0402]  133.07 17.69 270 top
CD139  -  [C_0402]  141.07 17.69 270 top
CD140  -  [C_0402]  153.65 17.69 270 top
CD142  -  [C_0402]  124.94 17.69 270 top
CD143  -  [C_0402]  113.01 26.76 90 top
CD144  -  [C_0402]  161.46 30.84 90 top
CD145  -  [C_0402]  113.13 30.95 90 top
CD146  -  [C_0402]  97.2 25.63 180 top
CD147  -  [C_0603]  97.38 30.44 180 top
CD148  -  [C_0402]  112.12 33.11 90 top
CD149  -  [C_0402]  105.77 20.66 270 top
CD150  -  [C_0402]  112.12 28.79 90 top
CD151  -  [C_0402]  104.88 20.66 270 top
CD152  -  [C_0402]  103.42 35.41 180 top
CD153  -  [C_0402]  97.2 23.73 180 top
CD154  -  [C_0402]  127.83 23.86 90 top
CD155  -  [C_0402]  113.13 33.11 90 top
CD156  -  [C_0402]  122.15 20.53 0 bottom
CD157  -  [C_0402]  127.83 28.94 90 top
CD158  -  [C_0402]  127.83 30.84 90 top
CD159  -  [C_0402]  115.01 35.41 0 top
CD160  -  [C_0402]  127.83 22.59 270 top
CD161  -  [C_0402]  113.13 28.79 90 top
CD162  -  [C_0402]  145.64 25.61 270 top
CD163  -  [C_0402]  145.64 30.69 90 top
CD164  -  [C_0402]  112.12 25.23 270 top
CD165  -  [C_0402]  146.66 26.88 90 top
CD166  -  [C_0402]  145.64 32.85 90 top
CD167  -  [C_0402]  136.24 35.41 180 top
CD168  -  [C_0402]  146.66 33.74 270 top
CD169  -  [C_0402]  161.46 32.87 90 top
CD170  -  [C_0402]  161.46 28.94 90 top
CD171  -  [C_0402]  152.12 20.53 0 bottom
CD172  -  [C_0402]  156.38 35.41 180 top
CD173  -  [C_0402]  134.08 35.41 180 top
CD174  -  [C_0402]  130.91 28.94 90 top
CD175  -  [C_0402]  130.91 31.73 270 top
CD176  -  [C_0402]  140.05 35.41 0 top
CD177  -  [C_0402]  156.69 20.53 180 bottom
CD178  -  [C_0402]  161.46 24.11 90 top
CD179  -  [C_0402]  151.81 35.41 180 top
CD180  -  [C_0402]  103.99 20.66 270 top
CD181  -  [C_0402]  120.24 20.53 0 bottom
CD182  -  [C_0603]  128.89 23.16 0 top
CD183  -  [C_0402]  138.79 20.53 0 bottom
CD184  -  [C_0402]  153.9 20.53 0 bottom
CD185  -  [C_0402]  94.88 40.08 270 top
CD186  -  [C_0402]  95.77 38.29 180 top
CD187  -  [C_0402]  153.01 39.2 0 top
CD196  -  [C_0603]  158.6 17.99 270 top
CD197  -  [C_0603]  95.61 19.26 90 top
CE3  -  [C_0402]  29.19 17.36 180 bottom
CE4  -  [C_0603]  27.98 21.17 0 bottom
CE10  -  [C_0402]  29.19 16.47 180 bottom
CE13  -  [C_0402]  184.89 70.95 90 top
CE14  -  [C_0402]  183.11 70.95 90 top
CE17  -  [C_0402]  182.35 55.79 270 top
CE21  -  [C_0402]  188.06 51.52 270 top
CE22  -  [C_0402]  191.95 50.38 180 bottom
CE38  -  [C_0402]  190.48 64.09 0 top
CE39  -  [C_0402]  188.14 67.01 180 bottom
CE40  -  [C_0402]  181.2 70.95 90 top
CE41  -  [C_0402]  179.68 55.79 270 top
CE42  -  [C_0603]  169.98 65.92 90 top
CE43  -  [C_0402]  187.17 60.36 270 bottom
CE45  -  [C_0603]  190.35 65.24 0 top
CE46  -  [C_0402]  170.1 61.43 180 top
CE47  -  [C_0402]  138.96 62.29 270 top
CE48  -  [C_0402]  106.4 45.04 90 bottom
CE49  -  [C_0402]  189.84 53.3 270 top
CE50  -  [C_0402]  177.06 58.63 0 bottom
CE51  -  [C_0402]  194.41 76.92 180 top
CE52  -  [C_0402]  180.44 73.24 90 top
CE53  -  [C_0402]  186.16 53.55 0 top
CE54  -  [C_0402]  188.06 64.27 180 bottom
CE55  -  [C_0402]  186.03 70.95 90 top
CE56  -  [C_0402]  191.03 53.04 0 bottom
CE57  -  [C_0402]  23.34 57.37 270 bottom
CE58  -  [C_0402]  190.03 67.22 270 bottom
CE59  -  [C_0402]  174.22 61.38 270 bottom
CE60  -  [C_0402]  188.95 70.06 180 top
CE61  -  [C_0402]  177.98 70.06 180 top
CE62  -  [C_0402]  183.24 52.36 270 top
CE63  -  [C_0402]  184 70.95 90 top
CE64  -  [C_0402]  183.24 55.79 270 top
CE65  -  [C_0402]  187.17 56.42 270 bottom
CE66  -  [C_0402]  149.45 39.84 180 top
CE67  -  [C_0402]  194.16 66.58 270 top
CE68  -  [C_0402]  176.94 56.47 0 bottom
CE70  -  [C_0201]  177.91 61.63 90 bottom
CE71  -  [C_0201]  177.91 60.96 270 bottom
CE72  -  [C_0402]  173.2 62.96 0 top
CH11  -  [C_0402]  40.49 36.03 90 bottom
CH12  -  [C_0402]  39.47 36.03 90 bottom
CH13  -  [C_0402]  206.48 21.04 270 bottom
CH14  -  [C_0402]  205.46 21.04 270 bottom
CH95  -  [C_0402]  15.04 14.56 180 top
CMOS1  -  [SHORTPADS]  148.95 42.88 270 top
CR24  -  [C_0201]  141.92 45.65 180 top
CR25  -  [C_0201]  142.53 46.24 90 top
CR26  -  [C_0201]  140.69 44.28 90 bottom
CS44  -  [C_0402]  189.33 38.19 180 bottom
CT1  -  [C_0201]  46.51 68.17 270 top
CT2  -  [C_0201]  47.78 67.59 90 top
CT3  -  [C_0201]  47.14 68.17 270 top
CT4  -  [C_0201]  48.41 67.59 90 top
CT5  -  [C_0201]  44.48 68.17 270 top
CT6  -  [C_0201]  45.11 67.59 90 top
CT7  -  [C_0201]  43.84 68.17 270 top
CT8  -  [C_0201]  45.75 67.59 90 top
CT9  -  [C_0603]  9.07 56.18 270 bottom
CT17  -  [C_0201]  49.64 58.23 0 top
CT18  -  [C_0201]  49.64 58.86 0 top
CT19  -  [C_0201]  51.85 59.11 0 top
CT20  -  [C_0201]  51.85 59.75 0 top
CT21  -  [C_0201]  49.64 60 0 top
CT22  -  [C_0201]  49.64 60.64 0 top
CT23  -  [C_0201]  51.91 60.88 0 top
CT24  -  [C_0201]  51.91 61.51 0 top
CT25  -  [C_0201]  51.84 56.57 0 top
CT26  -  [C_0201]  51.84 55.94 0 top
CT29  -  [C_0201]  49.64 61.78 0 top
CT30  -  [C_0201]  49.64 62.42 0 top
CT31  -  [C_0201]  51.84 62.99 0 top
CT32  -  [C_0201]  51.84 63.62 0 top
CT33  -  [C_0201]  49.64 63.43 0 top
CT34  -  [C_0201]  49.64 64.07 0 top
CT35  -  [C_0201]  49.64 65.59 0 top
CT36  -  [C_0201]  49.64 64.96 0 top
CT37  -  [C_0201]  35.15 62.24 180 top
CT38  -  [C_0201]  35.13 62.82 180 top
CT39  -  [C_0201]  35.93 64.08 180 top
CT40  -  [C_0201]  35.94 63.48 180 top
CT41  -  [C_0201]  51.5 65.44 0 top
CT42  -  [C_0201]  51.5 64.8 0 top
CT43  -  [C_0402]  35.84 66.89 270 top
CT44  -  [C_0402]  35.84 67.74 90 top
CT47  -  [C_0201]  41.24 38.31 0 top
CT50  -  [C_0201]  46.14 56.47 270 bottom
CT52  -  [C_0201]  35.97 55.8 270 top
CT53  -  [C_0402]  34.66 55.74 270 top
CT54  -  [C_0402]  32.91 55.75 270 top
CT55  -  [C_0402]  33.78 55.75 270 top
CT56  -  [C_0402]  32.03 55.75 270 top
CT57  -  [C_0201]  35.26 58.48 180 top
CT62  -  [C_0201]  49.05 61.4 90 bottom
CT63  -  [C_0201]  47.03 59.2 270 bottom
CT64  -  [C_0201]  50.25 55.08 0 bottom
CT65  -  [C_0201]  50.24 54.49 0 bottom
CT66  -  [C_0201]  47.59 59.2 270 bottom
CT67  -  [C_0201]  50.2 61.39 90 bottom
CT68  -  [C_0201]  49.63 61.39 90 bottom
CT71  -  [C_0201]  41.85 67.59 180 top
CT72  -  [C_0201]  42.53 67.5 0 top
CT74  -  [C_0201]  35.97 60.26 270 top
CT80  -  [C_0201]  42.53 68.13 0 top
CT81  -  [C_0201]  41.85 68.22 180 top
CT83  -  [C_0201]  34.7 60.26 270 top
CT84  -  [C_0201]  35.33 60.26 270 top
CT85  -  [C_0201]  34.1 60.26 180 top
CT86  -  [C_0201]  34.06 60.84 180 top
CT88  -  [C_0603]  31.57 48.71 180 top
CT89  -  [C_0603]  31.57 51.13 180 top
CT90  -  [C_0603]  31.57 49.92 180 top
CT91  -  [C_0201]  34.95 60.89 90 top
CT92  -  [C_0201]  35.59 60.89 90 top
CT93  -  [C_0201]  49.64 67.75 0 top
CT94  -  [C_0201]  49.64 67.12 0 top
CT95  -  [C_0402]  39.35 65.01 180 bottom
CT96  -  [C_0402]  41.45 64.77 90 bottom
CT97  -  [C_0402]  41.8 63.95 270 bottom
CT98  -  [C_0402]  40.56 64.77 90 bottom
CT99  -  [C_0201]  48.22 70.56 90 bottom
CT100  -  [C_0201]  40.53 67.62 90 top
CT101  -  [C_0201]  49.64 54.8 0 top
CT102  -  [C_0201]  49.64 55.56 0 top
CT103  -  [C_0201]  49.64 56.19 0 top
CT107  -  [C_0201]  51.84 57.97 0 top
CT108  -  [C_0201]  51.84 57.34 0 top
CT144  -  [C_0402]  24.65 66.34 90 top
CT149  -  [C_0201]  43.92 61.15 90 bottom
CT150  -  [C_0201]  45 56.49 270 bottom
CT151  -  [C_0402]  19.66 66.37 90 top
CT152  -  [C_0402]  28.8 65.24 180 top
CT153  -  [C_0201]  38.65 57.1 270 bottom
CT154  -  [C_0201]  44.27 60.55 180 bottom
CT155  -  [C_0201]  47.24 61.79 90 bottom
CT156  -  [C_0201]  47.83 61.79 90 bottom
CT157  -  [C_0201]  42.56 68.7 0 top
CT158  -  [C_0201]  43.1 65.72 270 bottom
CT159  -  [C_0201]  38.13 63.66 90 bottom
CT160  -  [C_0201]  44.48 65.58 180 bottom
CT161  -  [C_0201]  44.48 65.01 180 bottom
CT162  -  [C_0201]  42.44 64.97 90 bottom
CT163  -  [C_0201]  24.37 52.61 0 bottom
CT164  -  [C_0603]  23.31 50.58 180 bottom
CT165  -  [C_0603]  23.31 51.82 180 bottom
CT166  -  [C_0201]  47.04 70.58 90 bottom
CT167  -  [C_0201]  47.63 70.57 90 bottom
CT168  -  [C_0201]  43.71 68.12 270 bottom
CT169  -  [C_0201]  44.3 68.13 270 bottom
CT170  -  [C_0201]  38.08 58.57 90 bottom
CT171  -  [C_0201]  36.6 58.15 90 bottom
CT172  -  [C_0201]  35.46 54.02 90 top
CT173  -  [C_0201]  36.04 54.03 90 top
CT174  -  [C_0201]  38.7 63.67 90 bottom
CT175  -  [C_0201]  43.69 59.38 90 bottom
CT176  -  [C_0201]  43.04 59.67 90 bottom
CT177  -  [C_0201]  39.37 65.73 180 bottom
CT178  -  [C_0201]  38.05 57.1 270 bottom
CT179  -  [C_0201]  45.57 56.47 270 bottom
CZ78  -  [C_0402]  149.84 73.53 270 top
CZ82  -  [C_0402]  160.81 67.52 0 top
CZ83  -  [C_0402]  159.74 46.44 0 top
CZ84  -  [C_0402]  158.52 78.32 0 top
CZ85  -  [C_0402]  153.18 77.92 270 top
CZ86  -  [C_0402]  167.54 66.89 0 top
CZ87  -  [C_0402]  167.54 66 0 top
CZ89  -  [C_0402]  165.89 46.57 0 top
CZ90  -  [C_0402]  45.02 49.84 90 top
CZ91  -  [C_0402]  52.34 44.4 0 top
CZ92  -  [C_0402]  158.51 74.35 270 top
D72  -  [BAT54CW-7-F_SOT323-3]  190.86 28.03 270 top
D73  -  [BAT54CW-7-F_SOT323-3]  190.66 30.69 270 top
D75  -  [ESD101-B1-02ELS_TSSLP-2-4-2]  10.9 63.97 90 top
D76  -  [ESD101-B1-02ELS_TSSLP-2-4-2]  10.9 63.33 270 top
D77  -  [ESD101-B1-02ELS_TSSLP-2-4-2]  15.01 61.9 90 top
D78  -  [ESD101-B1-02ELS_TSSLP-2-4-2]  8.89 59.74 90 top
D79  -  [ESD101-B1-02ELS_TSSLP-2-4-2]  10.2 58.12 90 top
D80  -  [ESD101-B1-02ELS_TSSLP-2-4-2]  10.2 57.49 270 top
D81  -  [RB751S40T1G_SOD523-2]  163.68 16.21 180 top
D82  -  [ESD101-B1-02ELS_TSSLP-2-4-2]  12.95 59.35 90 top
D83  -  [ESD101-B1-02ELS_TSSLP-2-4-2]  12.95 58.71 270 top
D84  -  [ESD101-B1-02ELS_TSSLP-2-4-2]  10.2 63.4 90 bottom
D85  -  [ESD101-B1-02ELS_TSSLP-2-4-2]  10.2 62.76 270 bottom
D86  -  [ESD101-B1-02ELS_TSSLP-2-4-2]  10.35 55.57 270 top
D87  -  [ESD101-B1-02ELS_TSSLP-2-4-2]  14.07 66.06 180 top
D88  -  [ESD101-B1-02ELS_TSSLP-2-4-2]  10.05 57.15 270 bottom
D89  -  [ESD101-B1-02ELS_TSSLP-2-4-2]  10.05 57.91 90 bottom
D90  -  [ESD101-B1-02ELS_TSSLP-2-4-2]  10.2 60.79 90 bottom
D91  -  [ESD101-B1-02ELS_TSSLP-2-4-2]  10.2 60.16 270 bottom
D94  -  [BAT54CW-7-F_SOT323-3]  203.43 43.71 180 top
D122  -  [AZ5125-01HPR7G_SOD523-2]  13.98 12.73 270 top
D123  -  [BZT52C15LP-7_DFN1006-2-2]  11.42 55.73 270 top
DA1  -  [AZ5125-02SPR7G_SOT23-3]  17.25 34.15 0 bottom
DA2  -  [AZ5125-02SPR7G_SOT23-3]  17.25 23.81 180 bottom
DA3  -  [PJDLC05C_SOT23-3]  20.9 15.96 270 top
DA4  -  [PJDLC05C_SOT23-3]  27.92 17.99 180 top
DA5  -  [ESD207-B1-02EL_TSLP-2-19-2]  5.63 23.43 180 bottom
DA7  -  [ESD207-B1-02EL_TSLP-2-19-2]  5.44 21.42 270 top
DE11  -  [RB751S40T1G_SOD523-2]  187.15 70.38 180 bottom
DI1  -  [IP4292CZ10-TBR_XSON10_2P5X1]  17.77 39.09 90 bottom
DI2  -  [AZC199-02SPR7G_SOT23-3]  20.57 44.03 270 bottom
DI3  -  [AZC199-02SPR7G_SOT23-3]  57.25 69.69 90 bottom
DI4  -  [AZC199-02SPR7G_SOT23-3]  76.62 74.97 270 bottom
DI7  -  [PESD24VS2UT_SOT23-3]  17.45 57.08 90 bottom
DZ1  -  [RB751S40T1G_SOD523-2]  47.12 43.76 90 top
DZ2  -  [RB751S40T1G_SOD523-2]  45.97 43.76 90 top
DZ3  -  [RB751S40T1G_SOD523-2]  159.11 48.22 180 bottom
FD1  -  [FIDUCIAL_C40M80]  15.8 70.66 0 top
FD2  -  [FIDUCIAL_C40M80]  210.21 20.14 0 top
FD3  -  [FIDUCIAL_C40M80]  209.19 22.34 180 bottom
FD4  -  [FIDUCIAL_C40M80]  18.45 77.48 180 bottom
H1  -  [H_2P0]  10.2 70.12 0 top
H3  -  [H_1P8N]  5.7 17.12 0 top
H4  -  [H_2P0]  81.96 79.8 0 top
H6  -  [H_3P3]  188.2 23.12 0 top
H7  -  [H_2P0]  129.09 13.28 0 top
H9  -  [H_2P0]  182.82 79.8 0 top
H10  -  [H_3P3]  162.8 53.85 0 top
H11  -  [H_3P3]  40.5 72.3 0 top
H12  -  [H_2P0]  10.2 17.12 0 top
H13  -  [H_2P0]  214.81 15.47 0 top
H14  -  [H_3P3]  104 53.85 0 top
H15  -  [H_3P3]  162.8 74.85 0 top
H16  -  [H_3P3]  104 74.85 0 top
H17  -  [H_3P3]  203 50.12 0 top
H18  -  [H_2P0]  52.89 13.31 0 top
H19  -  [H_2P0]  110.04 13.31 0 top
H20  -  [EMIST_SUL-12A2M_1P]  17.18 53.62 180 bottom
H21  -  [EMIST_SUL-12A2M_1P]  26.08 44.92 270 bottom
H22  -  [EMIST_SUL-12A2M_1P]  17.18 36.62 180 bottom
H23  -  [H_2P3X1P8N]  199.67 79.8 0 top
H24  -  [EMIST_SUL-12A2M_1P]  9.7 53.36 0 top
H25  -  [EMIST_SUL-12A2M_1P]  9.7 36.86 0 top
H26  -  [H_3P2X0P8]  97.6 14.4 0 top
JAPS1  -  [ACES_50506-01841-P01_18P]  200.76 35.89 270 bottom
JBATT1  -  [FOX_GS73091-10272-7H_9P-T]  71.1 26.14 0 bottom
JCAM  -  [CVILU_CI1806M2HRP-NH_6P]  54.1 73.63 0 bottom
JDEG1  -  [HB_A531015-SCHR21_10P]  169.65 68.22 0 bottom
JEDP  -  [ACES_50398-04041-001_40P]  192.75 24.37 90 bottom
JFAN1  -  [ACES_50224-00401-001_4P]  165.62 18.37 270 bottom
JHP1  -  [SINGA_2SJ3095-022111F_6P-T]  11.82 25.51 270 bottom
JIO1  -  [JXT_FP270H-061G1AM_61P]  210.21 15.54 180 bottom
JKB1  -  [E-T_6710K-Y15M-31L_15P]  46.92 20.36 180 bottom
JLPDE1  -  [HB_A531015-SCHR21_10P]  179.65 71.22 0 bottom
JNGFF1  -  [CONCR_213AAAA32FA_67P]  31.25 38.77 0 bottom
JNGFF2  -  [CONCR_213MAAA32FA_67P-T]  183.15 23.29 90 bottom
JP100  -  [ACES_88266-05001_5P]  26.46 71.29 90 bottom
JPA1  -  [JUMP_43X39]  26.01 32.55 270 bottom
JPA2  -  [JUMP_43X39]  5.77 21.45 180 bottom
JPA3  -  [JUMP_43X39]  21.69 22.64 270 top
JRTC1  -  [ACES_50278-00201-001_2P]  14.59 10.64 117.2 bottom
JSPI1  -  [ACES_50696-0200M-P01_20P]  189.26 77.9 180 bottom
JSPK1  -  [ACES_50224-00401-001_4P]  25.78 13.82 90 bottom
JTAG1  -  [SHORTPADS]  171.3 60.92 270 bottom
JTP1  -  [ACES_50506-00841-P01_8P]  186.66 19.36 180 bottom
JTS  -  [CVILU_CI1806M2HRP-NH_6P]  71.65 74.56 90 bottom
JUART  -  [ACES_50207-00471-P01_4P-T]  51.03 22.17 90 bottom
JUSB2  -  [TE_C-PT13-067_9P-T]  14.23 48.61 90 bottom
JUSBC1  -  [JAE_DX07SA24XJ2_24P-T]  7.43 63.54 270 top
JXDP1  -  [SAMTE_BSH-030-01-L-D-A_60P]  78.6 73.05 180 top
L2  -  [MURAT_BLM15PX181SN1D_2P]  23.72 20.91 270 top
L3  -  [MURAT_BLM15PX181SN1D_2P]  25.5 20.91 270 top
L4  -  [MURAT_BLM15PX181SN1D_2P]  28.42 20.91 180 top
L5  -  [MURAT_BLM15PX181SN1D_2P]  30.2 21.42 270 top
L55  -  [INPAQ_MCM1012B900F06BP_4P]  61.72 71.17 270 bottom
LA2  -  [MURAT_BLM15PX600SN1D_2P]  31.85 26.33 90 bottom
LA3  -  [MURAT_BLM21PG600SN1D_L0805_2P]  22.71 21.31 90 bottom
LA4  -  [MURAT_BLM15PX600SN1D_2P]  28.13 24.22 0 bottom
LA6  -  [CHILI_PBY100505T-600Y-N_2P]  14.83 25.91 270 bottom
LA7  -  [CHILI_PBY100505T-600Y-N_2P]  20.68 23.88 270 bottom
LA14  -  [MURAT_BLM15BB220SN1D_2P]  37.18 24.85 180 top
LED10  -  [LED_27-11-T1D-CP1Q1RY-3C_2P]  2 8.4 90 top
LED11  -  [LED_27-11-T1D-CP1Q1RY-3C_2P]  2 4.8 90 top
LED12  -  [LED_27-11-T1D-CP1Q1RY-3C_2P]  2 15.6 90 top
LED13  -  [LED_27-11-T1D-CP1Q1RY-3C_2P]  2 1.2 90 top
LED14  -  [LED_27-11-T1D-CP1Q1RY-3C_2P]  2 12 90 top
LT1  -  [COILC_XFL4012-601MEC_2P]  35.6 49.56 180 top
LT14  -  [CHILI_PBY160808T-300Y-N_2P]  24.51 50.72 270 bottom
LT106  -  [TAI-T_HCB2012KF-121T50_2P]  19.81 55.9 270 top
MC3  -  [C_0402]  193.02 28.53 180 top
MD9  -  [PESD5V0U2BT_SOT23-3]  181.97 14.56 0 top
MD10  -  [PESD5V0U2BT_SOT23-3]  186.03 14.56 0 top
ML6  -  [MURAT_DLW21HN900SQ2L_4P]  15.65 59.43 180 top
ML7  -  [MURAT_DLW21HN900SQ2L_4P]  12.89 60.07 180 bottom
ML9  -  [INPAQ_MCM1012B900F06BP_4P]  80.31 75.52 180 bottom
ML10  -  [INPAQ_MCM1012B900F06BP_4P]  37.67 36.29 180 bottom
ML11  -  [INPAQ_MCM1012B900F06BP_4P]  22.73 45.98 180 bottom
ML12  -  [MURAT_DLW21SN670HQ2L_4P]  22.21 40.58 180 bottom
ML13  -  [MURAT_DLW21SN670HQ2L_4P]  23.18 38.29 180 bottom
NOREF  -  []  106.1 42.18 0 top
NOREF#2  -  []  123.86 41.47 0 top
NOREF#3  -  []  52.89 13.31 0 top
NOREF#4  -  []  162.8 74.85 0 top
NOREF#5  -  []  214.81 15.47 0 top
NOREF#6  -  []  162.8 53.85 0 top
NOREF#7  -  []  182.82 79.8 0 top
NOREF#8  -  []  96.88 44.45 0 top
NOREF#9  -  []  10.2 17.12 0 top
NOREF#10  -  []  40.5 72.3 0 top
NOREF#11  -  []  203 50.12 0 top
NOREF#12  -  []  81.96 79.8 0 top
NOREF#13  -  []  110.04 13.31 0 top
NOREF#14  -  []  188.2 23.12 0 top
NOREF#15  -  []  104 74.85 0 top
NOREF#16  -  []  129.09 13.28 0 top
NOREF#17  -  []  104 53.85 0 top
NOREF#18  -  []  51.46 26.2 0 top
NOREF#19  -  []  10.2 70.12 0 top
NOREF#20  -  []  30.58 -23.92 0 top
NOREF#21  -  []  167.56 27.69 180 bottom
NOREF#22  -  []  122.82 38.68 180 bottom
NOREF#23  -  []  138.9 39.99 180 bottom
PC100  -  [C_0402]  78.21 25.87 270 bottom
PC101  -  [C_0402]  75.67 22.82 270 bottom
PC102  -  [C_0402]  70.59 18.17 90 top
PC103  -  [C_0603]  26.01 78.32 270 top
PC104  -  [C_0402]  24.87 78.19 270 top
PC105  -  [C_0402]  23.98 78.19 270 top
PC106  -  [C_0402]  33.12 77.86 90 bottom
PC107  -  [C_0402]  31.73 77.81 90 bottom
PC108  -  [C_0805]  27.48 76.52 270 top
PC200  -  [C_0603]  50.6 49.46 90 top
PC201  -  [C_0603]  30.61 76.83 270 bottom
PC202  -  [C_0603]  35.98 77.81 180 bottom
PC203  -  [C_0402]  58.34 57.84 0 bottom
PC204  -  [C_0402]  91.34 74.63 0 top
PC205  -  [C_0402]  91.34 71.84 0 top
PC206  -  [C_0603]  49.62 75.24 270 bottom
PC207  -  [C_0603]  49.31 77.75 90 bottom
PC208  -  [C_0603]  45.26 78.55 270 top
PC209  -  [C_0603]  66.78 67.71 270 bottom
PC210  -  [C_0402]  59.93 66.85 180 top
PC211  -  [C_0402]  84.43 73.16 90 top
PC212  -  [C_0402]  84.94 70.77 270 top
PC213  -  [C_0402]  87.48 67.83 90 top
PC214  -  [C_0402]  62.41 15.33 180 top
PC215  -  [C_0402]  64.03 18.25 0 top
PC216  -  [C_0402]  56.95 16.6 180 top
PC217  -  [C_0402]  56.95 19.52 180 top
PC218  -  [C_0402]  60.55 36.38 270 top
PC247  -  [C_0603]  94.15 42.87 270 top
PC301  -  [C_0402]  50.9 36.28 0 top
PC302  -  [C_0805]  51.03 34.88 0 top
PC303  -  [C_0805]  51.03 33.11 0 top
PC304  -  [C_0805]  51.03 31.33 0 top
PC305  -  [C_0805]  51.03 33.11 0 bottom
PC306  -  [C_0805]  51.03 34.88 0 bottom
PC307  -  [C_0805]  51.03 31.33 0 bottom
PC309  -  [C_0603]  44.87 22.69 180 bottom
PC310  -  [C_0402]  43.54 23.83 90 bottom
PC311  -  [C_0402]  43.71 25.74 0 bottom
PC312  -  [C_0603]  45.95 31.07 0 bottom
PC313  -  [C_0805]  47.44 27.01 180 bottom
PC314  -  [C_0603]  73.05 38.05 0 top
PC315  -  [C_0603]  73.08 36.53 0 bottom
PC316  -  [C_0603]  73.06 35.01 0 bottom
PC317  -  [C_0603]  73.05 38.05 0 bottom
PC318  -  [C_0402]  40.36 24.27 90 bottom
PC319  -  [C_0603]  71.86 43.07 90 top
PC320  -  [C_0603]  73.06 35.01 0 top
PC321  -  [C_0603]  73.08 36.53 0 top
PC322  -  [C_0603]  47.35 28.53 180 bottom
PC323  -  [C_0603]  73.89 31.33 270 top
PC324  -  [C_0603]  68.63 31.37 270 bottom
PC325  -  [C_0603]  72.26 31.34 270 bottom
PC326  -  [C_0603]  70.47 31.33 270 bottom
PC327  -  [C_0603]  68.63 31.37 270 top
PC328  -  [C_0603]  70.47 31.33 270 top
PC329  -  [C_0603]  72.26 31.34 270 top
PC330  -  [C_0402]  39.47 25.18 270 bottom
PC331  -  [C_0402]  39.47 25.18 270 top
PC332  -  [C_0402]  39.27 28.91 0 top
PC333  -  [C_0603]  52.81 36.41 180 bottom
PC334  -  [C_0402]  44.3 34.13 270 bottom
PC335  -  [C_0402]  43.42 33.49 180 bottom
PC336  -  [C_0402]  42.51 34.38 0 bottom
PC337  -  [C_0603]  40.49 33.11 90 bottom
PC400  -  [C_0402]  162.92 64.3 270 bottom
PC401  -  [C_0402]  163.81 64.3 270 bottom
PC402  -  [C_0402]  173.41 58.63 180 bottom
PC403  -  [C_0402]  165.58 64.3 270 bottom
PC404  -  [C_0603]  171.74 55.71 0 top
PC405  -  [C_0402]  175.36 58.38 270 top
PC406  -  [C_0402]  167.03 60.03 0 top
PC407  -  [C_0603]  164.38 58.44 0 top
PC500  -  [C_0402]  89.76 22.44 270 top
PC501  -  [C_0402]  90.65 22.44 270 top
PC502  -  [C_0603]  93.13 22.34 270 bottom
PC503  -  [C_0603]  93.13 22.34 270 top
PC504  -  [C_0603]  86.34 22.5 270 top
PC505  -  [C_0603]  78.93 22.67 180 bottom
PC506  -  [C_0603]  78.91 21.42 180 bottom
PC507  -  [C_0603]  78.91 22.18 180 top
PC508  -  [C_0603]  78.91 20.15 180 bottom
PC509  -  [C_0603]  86.53 17.23 180 bottom
PC510  -  [C_0603]  86.27 23.83 0 top
PC511  -  [C_0402]  90.15 17.94 270 bottom
PC512  -  [C_0603]  59.98 43.54 180 top
PC513  -  [C_0402]  64.24 44.23 270 top
PC514  -  [C_0402]  63.35 44.23 270 top
PC515  -  [C_0603]  68.36 44.33 270 top
PC516  -  [C_0603]  66.75 44.34 270 top
PC517  -  [C_0603]  61.25 38.31 180 top
PC518  -  [C_0603]  55.92 49.11 180 bottom
PC519  -  [C_0603]  55.95 46.63 180 bottom
PC520  -  [C_0603]  55.92 47.84 180 bottom
PC521  -  [C_0603]  53.91 46.63 180 top
PC522  -  [C_0603]  53.89 49.11 180 top
PC523  -  [C_0603]  61.25 37.93 180 bottom
PC524  -  [C_0603]  60.74 39.84 0 top
PC525  -  [C_0402]  63.6 39.28 270 bottom
PC526  -  [C_0603]  78.91 20.91 180 top
PC527  -  [C_0603]  53.89 47.84 180 top
PC528  -  [C_0805]  68.54 44.38 270 bottom
PC529  -  [C_0805]  66.82 44.37 270 bottom
PC600  -  [C_0603]  169.08 34.38 180 top
PC601  -  [C_0603]  169.08 35.65 180 top
PC602  -  [C_0402]  168.96 36.79 180 top
PC603  -  [C_0402]  169.98 35.04 0 top
PC604  -  [C_0402]  172.83 23.19 270 top
PC605  -  [C_0402]  173.98 26.82 180 top
PC606  -  [C_0402]  172.49 28.91 0 top
PC607  -  [C_0402]  172.49 29.8 0 top
PC608  -  [C_0603]  166.09 26.95 270 top
PC609  -  [C_0402]  173.41 30.69 180 top
PC610  -  [C_0603]  164.78 23.29 90 top
PC611  -  [C_0603]  164.82 19.96 270 top
PC612  -  [C_0603]  167.36 19.96 270 top
PC613  -  [C_0603]  166.09 19.96 270 top
PC614  -  [C_0402]  166.55 31.96 180 top
PC615  -  [C_0603]  166.66 29.55 180 top
PC616  -  [C_0603]  166.66 30.82 180 top
PC617  -  [C_0402]  164.95 32.98 90 top
PC618  -  [C_0402]  163.93 29.42 180 top
PC700  -  [C_0402]  203.07 65.41 0 bottom
PC701  -  [C_0402]  201.88 57.57 270 bottom
PC702  -  [C_0402]  195.3 63.03 270 top
PC703  -  [C_0603]  199.99 60.16 180 top
PC704  -  [C_0402]  198.07 66.71 0 bottom
PC705  -  [C_0805]  196.7 63.8 270 top
PC706  -  [C_0805]  196.69 63.61 270 bottom
PC707  -  [C_0402]  203.98 63.62 180 bottom
PC708  -  [C_0805]  194.79 55.67 270 top
PC709  -  [C_0805]  194.79 57.4 90 top
PC710  -  [C_0805]  194.77 55.67 270 bottom
PC711  -  [C_0805]  194.74 57.4 90 bottom
PC712  -  [C_0402]  202.91 61.86 0 bottom
PC713  -  [C_0402]  203.05 62.25 0 top
PC800  -  [C_0402]  173.97 78.06 90 top
PC801  -  [C_0402]  170.66 70.82 90 top
PC802  -  [C_0805]  168.12 73.36 0 top
PC803  -  [C_0402]  176.63 76.16 0 top
PC804  -  [C_0402]  176.63 75.27 0 top
PC805  -  [C_0805]  176.76 77.56 0 top
PC806  -  [C_0402]  176.63 74.25 0 top
PC807  -  [C_0402]  169.62 79.84 0 top
PC900  -  [C_0402]  171.43 43.39 90 top
PC901  -  [C_0402]  166.73 38.19 90 top
PC902  -  [C_0805]  161.99 44.03 180 top
PC903  -  [C_0402]  171.43 41.61 90 top
PC904  -  [C_0402]  172.31 41.61 90 top
PC905  -  [C_0805]  171.81 40.47 270 top
PC906  -  [C_0402]  170.31 39.07 270 top
PC907  -  [C_0402]  163.6 40.45 270 top
PC1004  -  [C_0402]  64.49 51.9 270 bottom
PC1005  -  [C_0603]  64.62 55.71 90 bottom
PC1006  -  [C_0402]  62.33 51.01 180 top
PC1007  -  [C_0603]  65.42 52.88 0 bottom
PC1014  -  [C_0402]  69.7 46.82 270 top
PC1019  -  [C_0402]  67.79 46.44 90 bottom
PC1020  -  [C_0402]  65.89 46.06 90 top
PC1021  -  [C_0402]  66.9 48.09 90 top
PC1022  -  [C_0402]  68.68 48.22 180 bottom
PC1056  -  [C_0402]  71.13 53.16 0 bottom
PC1064  -  [C_0402]  71.48 55.84 270 bottom
PC1065  -  [C_0402]  71.1 52.28 0 bottom
PC1066  -  [C_0805]  66.65 62.16 90 top
PC1067  -  [C_0402]  73.64 56.9 0 bottom
PC1068  -  [C_0402]  67.54 58.17 90 top
PC1069  -  [C_0402]  73.89 56.73 90 top
PC1070  -  [C_0402]  70.59 48.22 90 top
PC1071  -  [C_0402]  67.54 58.17 90 bottom
PC1072  -  [C_0402]  69.52 59.39 180 top
PC1073  -  [C_D]  78.93 41.66 0 bottom
PC1074  -  [C_0402]  70.59 58.25 0 bottom
PC1075  -  [C_0402]  73.64 56.02 0 bottom
PC1076  -  [C_0402]  69.06 62.49 90 top
PC1077  -  [C_0402]  69.57 58.25 180 bottom
PC1078  -  [C_0402]  66.65 58.17 90 bottom
PC1079  -  [C_0402]  68.17 62.49 90 top
PC1080  -  [C_0402]  69.57 56.22 270 bottom
PC1081  -  [C_0402]  68.4 56.49 270 bottom
PC1082  -  [C_0603]  61.57 61.87 270 top
PC1083  -  [C_0402]  75.54 56.85 270 bottom
PC1084  -  [C_0402]  72.37 48.22 90 top
PC1085  -  [C_0402]  69.7 48.22 0 bottom
PC1086  -  [C_0603]  69.32 67.27 180 bottom
PC1087  -  [C_0402]  66.65 60.03 0 bottom
PC1088  -  [C_0402]  72.37 50 180 bottom
PC1089  -  [C_0402]  66.65 55.79 0 bottom
PC1090  -  [C_0402]  74.91 54.06 0 top
PC1091  -  [C_0402]  68.61 59.39 0 bottom
PC1092  -  [C_0402]  73.89 54.95 90 top
PC1093  -  [C_0805]  66.32 62.29 90 bottom
PC1094  -  [C_0402]  69.7 49.11 0 bottom
PC1095  -  [C_0402]  66.9 46.95 270 top
PC1096  -  [C_0402]  77.06 51.39 180 top
PC1097  -  [C_0402]  64.16 65.24 0 top
PC1098  -  [C_0402]  68.68 46.44 90 bottom
PC1099  -  [C_0402]  75.79 55.84 180 top
PC1100  -  [C_0603]  81.31 44.62 0 bottom
PC1101  -  [C_0603]  81.47 52.56 0 bottom
PC1102  -  [C_0603]  81.32 46.08 0 top
PC1103  -  [C_0402]  81.69 42.39 0 top
PC1104  -  [C_0402]  81.67 43.27 0 top
PC1105  -  [C_0603]  81.47 52.56 0 top
PC1106  -  [C_0402]  77.34 48.93 0 bottom
PC1107  -  [C_0603]  82.68 66.32 0 bottom
PC1108  -  [C_0603]  82.68 66.04 0 top
PC1109  -  [C_0805]  81.34 51.1 0 bottom
PC1110  -  [C_0402]  81.65 45.04 0 top
PC1111  -  [C_0402]  81.75 53.67 0 top
PC1112  -  [C_0402]  81.69 41.49 0 top
PC1113  -  [C_0402]  81.66 44.15 0 top
PC1114  -  [C_0603]  78.73 45.6 180 bottom
PC1115  -  [C_0603]  85.2 46.08 180 top
PC1116  -  [C_0402]  77.92 55.79 0 bottom
PC1117  -  [C_0402]  81.76 58.92 0 top
PC1118  -  [C_0402]  81.76 58.06 0 top
PC1119  -  [C_0603]  79.43 52.68 270 bottom
PC1120  -  [C_0603]  81.53 58.9 0 bottom
PC1121  -  [C_0603]  81.55 60.14 0 bottom
PC1122  -  [C_0805]  81.34 51.1 0 top
PC1123  -  [C_0402]  81.76 59.81 0 top
PC1124  -  [C_0402]  81.78 60.68 0 top
PC1125  -  [C_0603]  85.26 53.68 180 top
PC1126  -  [C_0402]  78.3 66.51 270 bottom
PC1127  -  [C_0402]  81.75 61.55 0 top
PC1128  -  [C_0402]  82.73 67.06 0 top
PC1129  -  [C_0603]  80.04 59.97 270 bottom
PC1130  -  [C_0603]  85.37 62.02 180 top
PC1131  -  [C_0402]  68.01 51.55 270 bottom
PC1132  -  [C_0402]  75.79 54.95 180 top
PC1133  -  [C_0402]  71.48 48.22 90 top
PC1134  -  [C_0402]  71.55 60.03 180 top
PC1135  -  [C_D]  78.93 36.97 0 bottom
PC1200  -  [C_0603]  128.94 62.06 0 top
PC1201  -  [C_0603]  132.88 62.06 180 top
PC1202  -  [C_0603]  129.01 59.46 90 top
PC1203  -  [C_0603]  130.28 59.46 90 top
PC1204  -  [C_0603]  131.55 59.46 90 top
PC1205  -  [C_0603]  132.82 59.46 90 top
PC1206  -  [C_0603]  132.94 65.17 270 top
PC1207  -  [C_0603]  131.67 65.17 270 top
